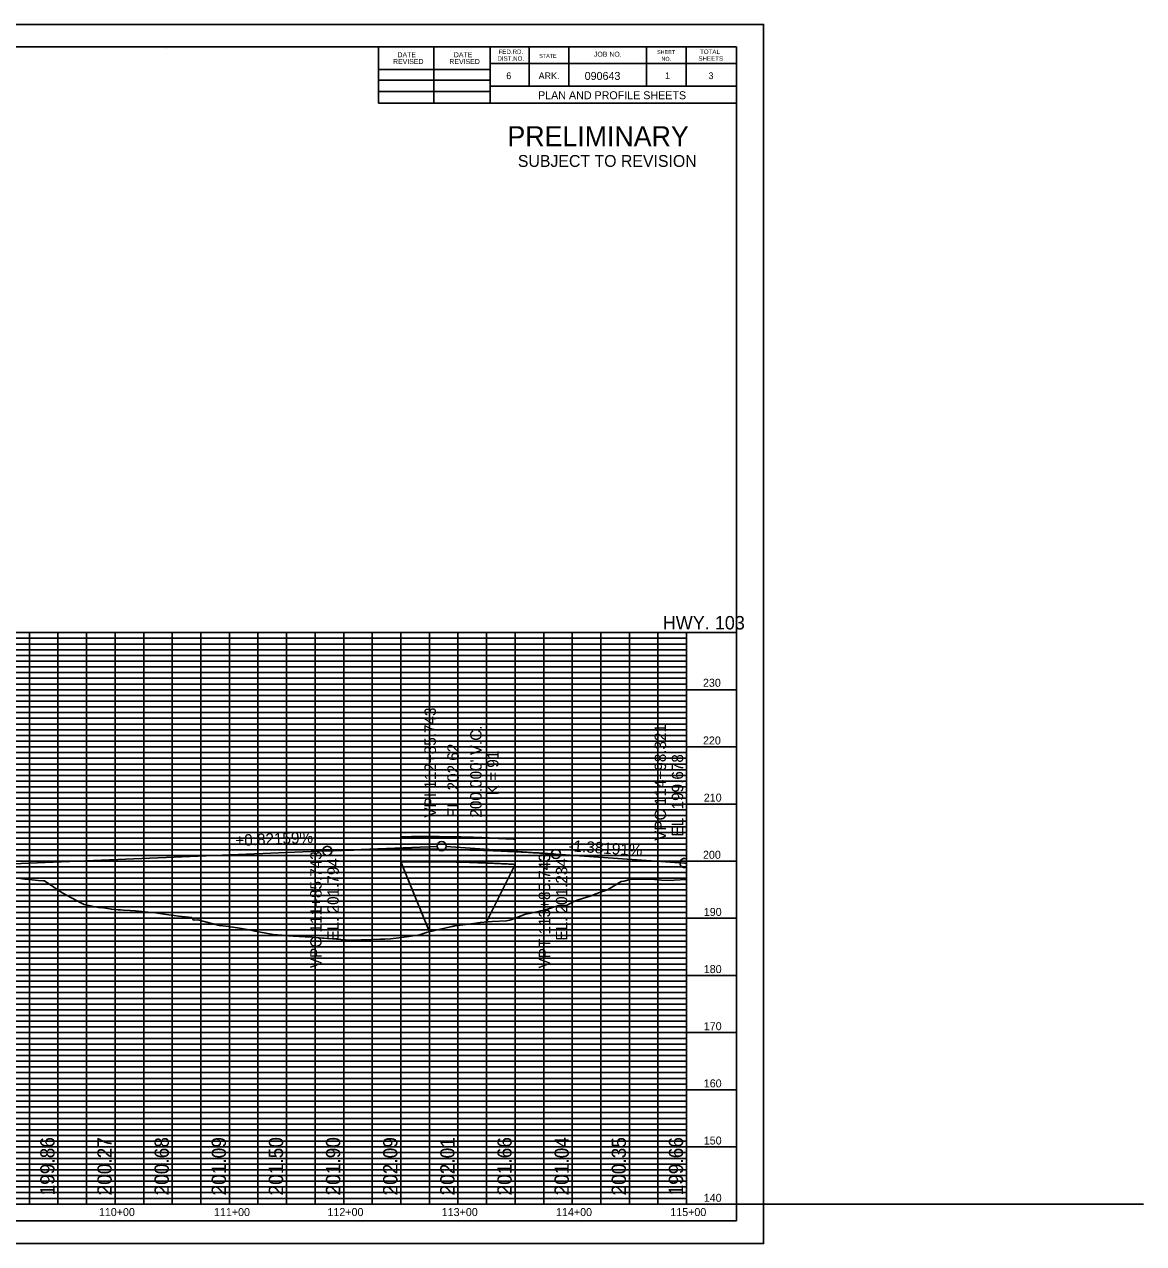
# Model space of a CAD drawing. Extents: x 1386057 to 1388056, y 1972278 to 1974778.
# Drawn here: x 1387077 to 1388056, y 1973493 to 1974560 of the extents above; entities that cross this region are included whole.
import ezdxf

# ---------------------------------------------------------------- set-up
doc = ezdxf.new("R2010")
doc.units = 0
for name, color, linetype in [('Default', 7, 'Continuous'), ('PROFILE_CELL', 7, 'Continuous'), ('PROFILE_DRAINAGE', 7, 'Continuous'), ('PROFILES_1', 7, 'Continuous'), ('PROFILES_TX_GRADES', 7, 'Continuous'), ('PROFILES_TX_STRIP', 7, 'Continuous'), ('PROFILES_TX_VPI', 7, 'Continuous'), ('R_Border', 7, 'Continuous'), ('R_Border Prem', 7, 'Continuous'), ('R_Grid', 7, 'Continuous'), ('R_No Plot', 7, 'Continuous'), ('X_PROFILES_1', 7, 'Continuous')]:
    doc.layers.add(name, color=color, linetype=linetype)

msp = doc.modelspace()

# ---------------------------------------------------------------- linework, layer by layer
at = {"layer": 'PROFILE_CELL'}
msp.add_line((1386156.5, 1973527.8), (1388056.5, 1973527.8), dxfattribs=at)
at = {"layer": 'PROFILE_DRAINAGE'}
for p, q in [((1387406.5, 1973827.2), (1387406.5, 1973849.2)), ((1387506.5, 1973825), (1387506.5, 1973847.1)), ((1387406.5, 1973827.2), (1387406.5, 1973761)), ((1387406.5, 1973827.2), (1387431.5, 1973765.9)), ((1387506.5, 1973825), (1387481.5, 1973774.6)), ((1387506.5, 1973825), (1387506.5, 1973777.8))]:
    msp.add_line(p, q, dxfattribs=at)
for points in [[(1387406.5, 1973849.2), (1387439.8, 1973849.4), (1387473.2, 1973848.7), (1387506.5, 1973847.1)], [(1387406.5, 1973827.2), (1387439.8, 1973827.4), (1387473.2, 1973826.7), (1387506.5, 1973825)]]:
    msp.add_open_spline(points, degree=2, dxfattribs=at)
at = {"layer": 'PROFILES_1'}
for p, q in [((1386761.5, 1973812.9), (1387342.2, 1973836.8)), ((1387542.2, 1973834), (1387654.8, 1973826.2)), ((1387654.8, 1973826.2), (1387656.5, 1973826.1))]:
    msp.add_line(p, q, dxfattribs=at)
msp.add_spline([(1387342.2, 1973836.8), (1387346.2, 1973836.9), (1387350.2, 1973837.1), (1387354.2, 1973837.2), (1387358.2, 1973837.4), (1387362.2, 1973837.5), (1387366.2, 1973837.6), (1387370.2, 1973837.7), (1387374.2, 1973837.8), (1387378.2, 1973837.9), (1387382.2, 1973838), (1387386.2, 1973838), (1387390.2, 1973838.1), (1387394.2, 1973838.2), (1387398.2, 1973838.2), (1387402.2, 1973838.2), (1387406.2, 1973838.3), (1387410.2, 1973838.3), (1387414.2, 1973838.3), (1387418.2, 1973838.3), (1387422.2, 1973838.3), (1387426.2, 1973838.3), (1387430.2, 1973838.3), (1387434.2, 1973838.2), (1387438.2, 1973838.2), (1387442.2, 1973838.1), (1387446.2, 1973838.1), (1387450.2, 1973838), (1387454.2, 1973837.9), (1387458.2, 1973837.8), (1387462.2, 1973837.7), (1387466.2, 1973837.6), (1387470.2, 1973837.5), (1387474.2, 1973837.4), (1387478.2, 1973837.3), (1387482.2, 1973837.1), (1387486.2, 1973837), (1387490.2, 1973836.8), (1387494.2, 1973836.7), (1387498.2, 1973836.5), (1387502.2, 1973836.3), (1387506.2, 1973836.1), (1387510.2, 1973835.9), (1387514.2, 1973835.7), (1387518.2, 1973835.5), (1387522.2, 1973835.2), (1387526.2, 1973835), (1387530.2, 1973834.8), (1387534.2, 1973834.5), (1387538.2, 1973834.2), (1387542.2, 1973834)], degree=3, dxfattribs=at)
at = {"layer": 'PROFILES_TX_GRADES'}
for p, q in [((1387342.2, 1973836.8), (1387438.2, 1973840.7)), ((1387542.2, 1973834), (1387446.2, 1973840.6)), ((1387654.8, 1973826.2), (1387656.5, 1973826.1))]:
    msp.add_line(p, q, dxfattribs=at)
for centre in [(1387442.2, 1973840.9), (1387342.2, 1973836.8), (1387542.2, 1973834)]:
    msp.add_circle(centre, 4, dxfattribs=at)
msp.add_arc((1387654.8, 1973826.2), 4, 65.1852, 294.8148, dxfattribs=at)
at = {"layer": 'R_Border'}
for p, q in [((1386119.2, 1974540.4), (1387700.1, 1974540.4)), ((1387201.3, 1974539.1), (1387201.3, 1974539.1)), ((1387201.3, 1974539.1), (1387201.3, 1974539.1)), ((1387386.9, 1974491), (1387386.9, 1974540.4)), ((1387435.3, 1974491), (1387435.3, 1974540.4)), ((1387484.6, 1974540.4), (1387484.6, 1974491)), ((1387518.8, 1974540.4), (1387518.8, 1974505.7)), ((1387553.5, 1974540.4), (1387553.5, 1974505.7)), ((1387621.4, 1974540.4), (1387621.4, 1974505.7)), ((1387656.1, 1974540.4), (1387656.1, 1974505.7)), ((1387700.1, 1973513.1), (1387700.1, 1974540.4)), ((1387700.1, 1974525.7), (1387484.6, 1974525.7)), ((1387386.9, 1974520.3), (1387484.6, 1974520.3)), ((1387386.9, 1974511), (1387484.6, 1974511)), ((1387700.1, 1974505.7), (1387484.6, 1974505.7)), ((1387499.4, 1974505.7), (1387700.1, 1974505.7)), ((1387386.9, 1974501.3), (1387484.6, 1974501.3)), ((1387700.1, 1974491), (1387386.9, 1974491)), ((1387700.1, 1974027.8), (1386119.2, 1974027.8)), ((1387106.5, 1973527.8), (1387106.5, 1974027.8)), ((1387156.5, 1973527.8), (1387156.5, 1974027.8)), ((1387206.5, 1973527.8), (1387206.5, 1974027.8)), ((1387256.5, 1973527.8), (1387256.5, 1974027.8)), ((1387306.5, 1973527.8), (1387306.5, 1974027.8)), ((1387356.5, 1973527.8), (1387356.5, 1974027.8)), ((1387406.5, 1973527.8), (1387406.5, 1974027.8)), ((1387456.5, 1973527.8), (1387456.5, 1974027.8)), ((1387506.5, 1973527.8), (1387506.5, 1974027.8)), ((1387556.5, 1973527.8), (1387556.5, 1974027.8)), ((1387606.5, 1973527.8), (1387606.5, 1974027.8)), ((1387656.5, 1973527.8), (1387656.5, 1974027.8)), ((1387700.1, 1973977.8), (1386119.2, 1973977.8)), ((1387700.1, 1973927.8), (1386119.2, 1973927.8)), ((1387700.1, 1973877.8), (1386119.2, 1973877.8)), ((1387700.1, 1973827.8), (1386119.2, 1973827.8)), ((1387700.1, 1973777.8), (1386119.2, 1973777.8)), ((1387700.1, 1973727.8), (1386119.2, 1973727.8)), ((1387700.1, 1973677.8), (1386119.2, 1973677.8)), ((1387700.1, 1973627.8), (1386119.2, 1973627.8)), ((1387700.1, 1973577.8), (1386119.2, 1973577.8)), ((1387700.1, 1973527.8), (1386119.2, 1973527.8)), ((1387700.1, 1973513.1), (1386119.2, 1973513.1))]:
    msp.add_line(p, q, dxfattribs=at)
at = {"layer": 'R_Grid'}
for p, q in [((1387081.5, 1973527.8), (1387081.5, 1974027.8)), ((1387131.5, 1973527.8), (1387131.5, 1974027.8)), ((1387181.5, 1973527.8), (1387181.5, 1974027.8)), ((1387231.5, 1973527.8), (1387231.5, 1974027.8)), ((1387281.5, 1973527.8), (1387281.5, 1974027.8)), ((1387331.5, 1973527.8), (1387331.5, 1974027.8)), ((1387381.5, 1973527.8), (1387381.5, 1974027.8)), ((1387431.5, 1973527.8), (1387431.5, 1974027.8)), ((1387481.5, 1973527.8), (1387481.5, 1974027.8)), ((1387531.5, 1973527.8), (1387531.5, 1974027.8)), ((1387581.5, 1973527.8), (1387581.5, 1974027.8)), ((1387631.5, 1973527.8), (1387631.5, 1974027.8)), ((1387656.5, 1974022.8), (1386156.5, 1974022.8)), ((1387656.5, 1974017.8), (1386156.5, 1974017.8)), ((1387656.5, 1974012.8), (1386156.5, 1974012.8)), ((1387656.5, 1974007.8), (1386156.5, 1974007.8)), ((1387656.5, 1974002.8), (1386156.5, 1974002.8)), ((1387656.5, 1973997.8), (1386156.5, 1973997.8)), ((1387656.5, 1973992.8), (1386156.5, 1973992.8)), ((1387656.5, 1973987.8), (1386156.5, 1973987.8)), ((1387656.5, 1973982.8), (1386156.5, 1973982.8)), ((1387656.5, 1973972.8), (1386156.5, 1973972.8)), ((1387656.5, 1973967.8), (1386156.5, 1973967.8)), ((1387656.5, 1973962.8), (1386156.5, 1973962.8)), ((1387656.5, 1973957.8), (1386156.5, 1973957.8)), ((1387656.5, 1973952.8), (1386156.5, 1973952.8)), ((1387656.5, 1973947.8), (1386156.5, 1973947.8)), ((1387656.5, 1973942.8), (1386156.5, 1973942.8)), ((1387656.5, 1973937.8), (1386156.5, 1973937.8)), ((1387656.5, 1973932.8), (1386156.5, 1973932.8)), ((1387656.5, 1973922.8), (1386156.5, 1973922.8)), ((1387656.5, 1973917.8), (1386156.5, 1973917.8)), ((1387656.5, 1973912.8), (1386156.5, 1973912.8)), ((1387656.5, 1973907.8), (1386156.5, 1973907.8)), ((1387656.5, 1973902.8), (1386156.5, 1973902.8)), ((1387656.5, 1973897.8), (1386156.5, 1973897.8)), ((1387656.5, 1973892.8), (1386156.5, 1973892.8)), ((1387656.5, 1973887.8), (1386156.5, 1973887.8)), ((1387656.5, 1973882.8), (1386156.5, 1973882.8)), ((1387656.5, 1973872.8), (1386156.5, 1973872.8)), ((1387656.5, 1973867.8), (1386156.5, 1973867.8)), ((1387656.5, 1973862.8), (1386156.5, 1973862.8)), ((1387656.5, 1973857.8), (1386156.5, 1973857.8)), ((1387656.5, 1973852.8), (1386156.5, 1973852.8)), ((1387656.5, 1973847.8), (1386156.5, 1973847.8)), ((1387656.5, 1973842.8), (1386156.5, 1973842.8)), ((1387656.5, 1973837.8), (1386156.5, 1973837.8)), ((1387656.5, 1973832.8), (1386156.5, 1973832.8)), ((1387656.5, 1973822.8), (1386156.5, 1973822.8)), ((1387656.5, 1973817.8), (1386156.5, 1973817.8)), ((1387656.5, 1973812.8), (1386156.5, 1973812.8)), ((1387656.5, 1973807.8), (1386156.5, 1973807.8)), ((1387656.5, 1973802.8), (1386156.5, 1973802.8)), ((1387656.5, 1973797.8), (1386156.5, 1973797.8)), ((1387656.5, 1973792.8), (1386156.5, 1973792.8)), ((1387656.5, 1973787.8), (1386156.5, 1973787.8)), ((1387656.5, 1973782.8), (1386156.5, 1973782.8)), ((1387656.5, 1973772.8), (1386156.5, 1973772.8)), ((1387656.5, 1973767.8), (1386156.5, 1973767.8)), ((1387656.5, 1973762.8), (1386156.5, 1973762.8)), ((1387656.5, 1973757.8), (1386156.5, 1973757.8)), ((1387656.5, 1973752.8), (1386156.5, 1973752.8)), ((1387656.5, 1973747.8), (1386156.5, 1973747.8)), ((1387656.5, 1973742.8), (1386156.5, 1973742.8)), ((1387656.5, 1973737.8), (1386156.5, 1973737.8)), ((1387656.5, 1973732.8), (1386156.5, 1973732.8)), ((1387656.5, 1973722.8), (1386156.5, 1973722.8)), ((1387656.5, 1973717.8), (1386156.5, 1973717.8)), ((1387656.5, 1973712.8), (1386156.5, 1973712.8)), ((1387656.5, 1973707.8), (1386156.5, 1973707.8)), ((1387656.5, 1973702.8), (1386156.5, 1973702.8)), ((1387656.5, 1973697.8), (1386156.5, 1973697.8)), ((1387656.5, 1973692.8), (1386156.5, 1973692.8)), ((1387656.5, 1973687.8), (1386156.5, 1973687.8)), ((1387656.5, 1973682.8), (1386156.5, 1973682.8)), ((1387656.5, 1973672.8), (1386156.5, 1973672.8)), ((1387656.5, 1973667.8), (1386156.5, 1973667.8)), ((1387656.5, 1973662.8), (1386156.5, 1973662.8)), ((1387656.5, 1973657.8), (1386156.5, 1973657.8)), ((1387656.5, 1973652.8), (1386156.5, 1973652.8)), ((1387656.5, 1973647.8), (1386156.5, 1973647.8)), ((1387656.5, 1973642.8), (1386156.5, 1973642.8)), ((1387656.5, 1973637.8), (1386156.5, 1973637.8)), ((1387656.5, 1973632.8), (1386156.5, 1973632.8)), ((1387656.5, 1973622.8), (1386156.5, 1973622.8)), ((1387656.5, 1973617.8), (1386156.5, 1973617.8)), ((1387656.5, 1973612.8), (1386156.5, 1973612.8)), ((1387656.5, 1973607.8), (1386156.5, 1973607.8)), ((1387656.5, 1973602.8), (1386156.5, 1973602.8)), ((1387656.5, 1973597.8), (1386156.5, 1973597.8)), ((1387656.5, 1973592.8), (1386156.5, 1973592.8)), ((1387656.5, 1973587.8), (1386156.5, 1973587.8)), ((1387656.5, 1973582.8), (1386156.5, 1973582.8)), ((1387656.5, 1973572.8), (1386156.5, 1973572.8)), ((1387656.5, 1973567.8), (1386156.5, 1973567.8)), ((1387656.5, 1973562.8), (1386156.5, 1973562.8)), ((1387656.5, 1973557.8), (1386156.5, 1973557.8)), ((1387656.5, 1973552.8), (1386156.5, 1973552.8)), ((1387656.5, 1973547.8), (1386156.5, 1973547.8)), ((1387656.5, 1973542.8), (1386156.5, 1973542.8)), ((1387656.5, 1973537.8), (1386156.5, 1973537.8)), ((1387656.5, 1973532.8), (1386156.5, 1973532.8))]:
    msp.add_line(p, q, dxfattribs=at)
at = {"layer": 'R_No Plot'}
for p, q in [((1386057.2, 1974559.9), (1387723.9, 1974559.9)), ((1386057.2, 1973493.2), (1387723.8, 1973493.2))]:
    msp.add_line(p, q, dxfattribs=at)
msp.add_lwpolyline([(1386057.2, 1974559.9), (1387723.9, 1974559.9), (1387723.9, 1973493.2), (1386057.2, 1973493.2)], close=True, dxfattribs=at)
at = {"layer": 'X_PROFILES_1'}
for points in [[(1387073.5, 1973812.5), (1387077.4, 1973812.2), (1387083.8, 1973811.6), (1387089.2, 1973810.8), (1387093.8, 1973810.6), (1387094.7, 1973810.5), (1387103, 1973805), (1387110.1, 1973800.2), (1387110.7, 1973799.8), (1387126.5, 1973791.5), (1387129.4, 1973789.9), (1387130.5, 1973789.7), (1387130.7, 1973789.7), (1387142.1, 1973787.4), (1387142.8, 1973787.3), (1387146.2, 1973787), (1387153.2, 1973785.7), (1387159.2, 1973785.3), (1387161.2, 1973785.2), (1387163.8, 1973784.8), (1387169.8, 1973784.6), (1387174.2, 1973784.3), (1387175.6, 1973784.2), (1387177, 1973784), (1387188.4, 1973783), (1387191.9, 1973782.5), (1387197.4, 1973781.6), (1387205.5, 1973780.7), (1387208.3, 1973780.3), (1387212.1, 1973779.7), (1387223.6, 1973778.4), (1387224.7, 1973776.9), (1387225.2, 1973776.1), (1387228.8, 1973776.4), (1387241, 1973773.2), (1387247.7, 1973771.5), (1387256.3, 1973770.6), (1387257.4, 1973770.5), (1387263.5, 1973769.6), (1387273.8, 1973767.7), (1387278.8, 1973766.7), (1387290.1, 1973764.6), (1387294.9, 1973763.6), (1387306.5, 1973762.7), (1387308.3, 1973762.6), (1387312.3, 1973762.3), (1387322.9, 1973761.6), (1387329, 1973761.2), (1387338.1, 1973760.5), (1387339.2, 1973760.4), (1387353.9, 1973759.3), (1387355.6, 1973759.1), (1387357, 1973759), (1387358.2, 1973759), (1387362.2, 1973758.6), (1387371.8, 1973758.9), (1387371.9, 1973758.9), (1387381.4, 1973759.3), (1387388.3, 1973759.6), (1387392.4, 1973759.7), (1387397.4, 1973759.9), (1387404.7, 1973760.8), (1387411.4, 1973761.6)], [(1387411.4, 1973761.6), (1387411.4, 1973761.7), (1387411.5, 1973761.7), (1387421, 1973763.2), (1387423.8, 1973763.6), (1387428.9, 1973765.3), (1387437.4, 1973767.3), (1387450, 1973770.4), (1387451.5, 1973770.7), (1387452, 1973770.8), (1387452.8, 1973771), (1387453.8, 1973771.2), (1387470.1, 1973773.4), (1387476, 1973774.2), (1387486.5, 1973774.9), (1387499, 1973775.7), (1387501.8, 1973776.1), (1387502.9, 1973776.4), (1387515.6, 1973781.3), (1387519.2, 1973782.1), (1387531.5, 1973784.8), (1387535.6, 1973786.1), (1387544.7, 1973789.1), (1387551.4, 1973789.1), (1387552, 1973789.4), (1387557.9, 1973792.5), (1387561.6, 1973793.9), (1387568.3, 1973796.1), (1387572.2, 1973797.3), (1387580.4, 1973800.4), (1387587.5, 1973802.8), (1387599.4, 1973809.9), (1387601.6, 1973810.2), (1387607.1, 1973811.8), (1387625.2, 1973812.1), (1387625.3, 1973812.1), (1387625.3, 1973812.1), (1387625.3, 1973812.1), (1387625.4, 1973812.1), (1387634.5, 1973811.1), (1387640.2, 1973810.9), (1387645.8, 1973811.2), (1387656.5, 1973811.8)]]:
    msp.add_lwpolyline(points, dxfattribs=at)

# ---------------------------------------------------------------- texts
at = {"layer": 'Default'}
for s, p in [('230', (1387670.9, 1973980.4)), ('220', (1387670.9, 1973929.9)), ('210', (1387671.6, 1973879.9)), ('200', (1387670.9, 1973829.9)), ('190', (1387671.6, 1973779.9)), ('180', (1387671.6, 1973729.9)), ('170', (1387671.6, 1973679.9)), ('160', (1387671.6, 1973629.9)), ('150', (1387671.6, 1973579.9)), ('140', (1387671.6, 1973529.8)), ('110+00', (1387142.3, 1973517.3)), ('111+00', (1387243, 1973517.3)), ('112+00', (1387342.3, 1973517.3)), ('113+00', (1387442.3, 1973517.3)), ('114+00', (1387542.3, 1973517.3)), ('115+00', (1387642.3, 1973517.3))]:
    msp.add_text(s, height=7, dxfattribs=at).set_placement(p)
at = {"layer": 'PROFILES_TX_GRADES'}
for s, rotation, p in [('+0.82159%', 2.3523, (1387261.9, 1973841)), ('-1.38191%', 356.0474, (1387553, 1973836.5))]:
    msp.add_text(s, height=10, rotation=rotation, dxfattribs=at).set_placement(p)
at = {"layer": 'PROFILES_TX_STRIP'}
for s, p in [('199.86', (1387103.5, 1973535.3)), ('200.27', (1387153.5, 1973535.3)), ('200.68', (1387203.5, 1973535.3)), ('201.09', (1387253.5, 1973535.3)), ('201.50', (1387303.5, 1973535.3)), ('201.90', (1387353.5, 1973535.3)), ('202.09', (1387403.5, 1973535.3)), ('202.01', (1387453.5, 1973535.3)), ('201.66', (1387503.5, 1973535.3)), ('201.04', (1387553.5, 1973535.3)), ('200.35', (1387603.5, 1973535.3)), ('199.66', (1387653.5, 1973535.3))]:
    msp.add_text(s, height=12.5, rotation=90, dxfattribs=at).set_placement(p)
at = {"layer": 'PROFILES_TX_VPI'}
for s, p in [('VPI 112+85.743', (1387437.2, 1973865.9)), ("200.000' V.C.", (1387477.2, 1973865.9)), ('VPC 114+98.321', (1387638.6, 1973845.6)), ('EL. 202.62', (1387457.2, 1973865.9)), ('K = 91', (1387492, 1973885.4)), (' EL. 199.678', (1387653.6, 1973845.6)), ('VPC 111+85.743', (1387337.2, 1973734.2)), ('VPT 113+85.743', (1387537.2, 1973734)), (' EL. 201.794', (1387352.2, 1973754.6)), (' EL. 201.234', (1387552.2, 1973754.6))]:
    msp.add_text(s, height=10, rotation=90, dxfattribs=at).set_placement(p)
at = {"layer": 'R_Border'}
for s, height, p in [('FED.RD.', 3.91, (1387492, 1974534)), ('JOB NO.', 4.4, (1387575.5, 1974531.6)), ('SHEET', 3.42, (1387630.7, 1974534)), ('TOTAL', 3.91, (1387668.3, 1974534)), ('REVISED', 4.4, (1387399.7, 1974525.2)), ('DATE', 4.4, (1387403.6, 1974531.1)), ('REVISED', 4.4, (1387449, 1974525.2)), ('DATE', 4.4, (1387452.9, 1974531.1)), ('DIST.NO.', 3.91, (1387491, 1974528.1)), ('STATE', 3.42, (1387527.6, 1974530.6)), ('NO.', 3.42, (1387634.6, 1974528.1)), ('SHEETS', 3.91, (1387666.9, 1974528.1)), ('6', 5.86, (1387498.8, 1974512)), ('ARK.', 5.86, (1387527.1, 1974512)), ('090643', 7, (1387567.4, 1974511.3)), ('1', 5.86, (1387637.7, 1974512)), ('3', 5.86, (1387675.7, 1974512)), ('PLAN AND PROFILE SHEETS', 7, (1387526.6, 1974494.4)), ('HWY. 103', 11.79, (1387635.7, 1974030.5))]:
    msp.add_text(s, height=height, dxfattribs=at).set_placement(p)
at = {"layer": 'R_Border Prem'}
for s, height, p in [('PRELIMINARY', 17.5, (1387499.8, 1974453.3)), ('SUBJECT TO REVISION', 10.376, (1387508.9, 1974435.2))]:
    msp.add_text(s, height=height, dxfattribs=at).set_placement(p)

doc.saveas('drawing.dxf')
